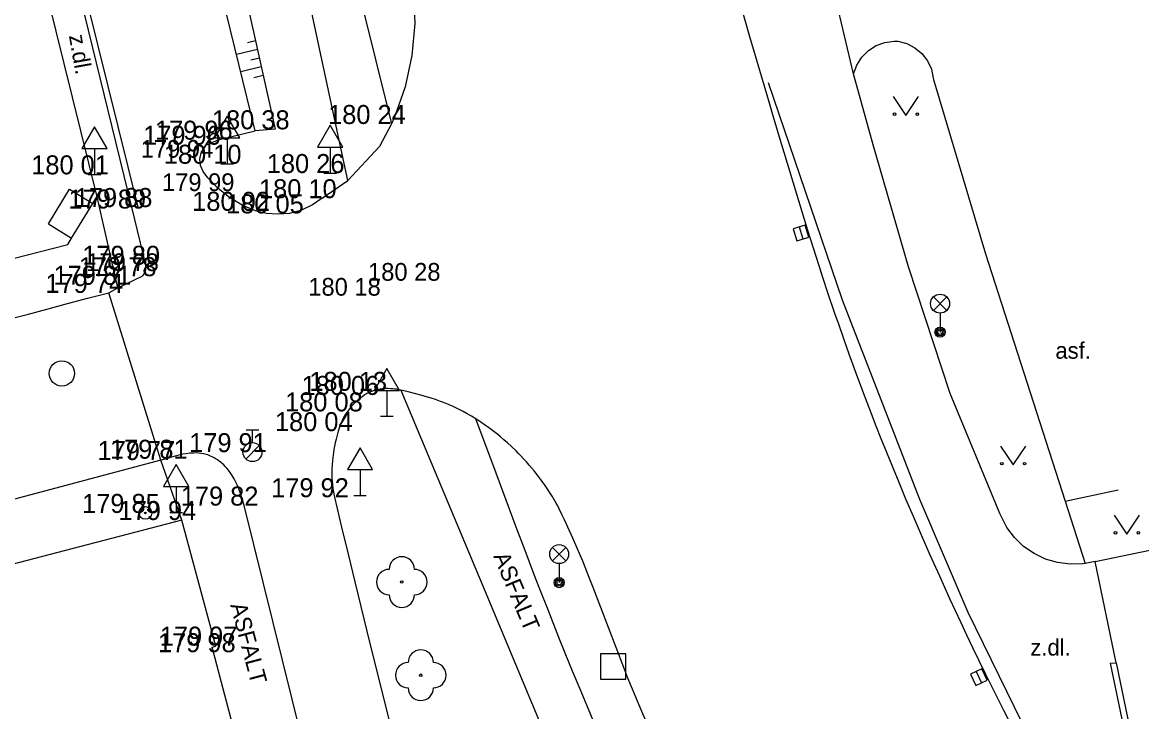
# Model space of a CAD drawing. Extents: x -538441 to -536770, y -1181008 to -1179809.
# Drawn here: x -537786.52 to -537742.3, y -1180705.34 to -1180678.12 of the extents above; entities that cross this region are included whole.
import ezdxf

# ---------------------------------------------------------------- set-up
doc = ezdxf.new("R2010")
doc.units = 0
for name, color, linetype in [('Vrstva 10', 7, 'Continuous'), ('Vrstva 11', 7, 'Continuous'), ('Vrstva 14', 7, 'Continuous'), ('Vrstva 15', 7, 'Continuous'), ('Vrstva 22', 7, 'Continuous'), ('Vrstva 25', 7, 'Continuous'), ('Vrstva 26', 7, 'Continuous'), ('Vrstva 27', 7, 'Continuous'), ('Vrstva 28', 7, 'Continuous'), ('Vrstva 33', 7, 'Continuous'), ('Vrstva 34', 7, 'Continuous'), ('Vrstva 36', 7, 'Continuous'), ('Vrstva 4', 7, 'Continuous'), ('Vrstva 40', 7, 'Continuous'), ('Vrstva 5', 7, 'Continuous'), ('Vrstva 7', 7, 'Continuous'), ('Vrstva 9', 7, 'Continuous')]:
    doc.layers.add(name, color=color, linetype=linetype)

msp = doc.modelspace()

# ---------------------------------------------------------------- linework, layer by layer
at = {"layer": 'Vrstva 10'}
for p, q in [((-537777.32, -1180682.4), (-537779.78, -1180672.39)), ((-537785.13, -1180673.46), (-537782.2, -1180685.47)), ((-537755.48, -1180686.34), (-537756.199, -1180683.987)), ((-537774.67, -1180685.06), (-537773.66, -1180684.36)), ((-537782.2, -1180685.47), (-537781.65, -1180687.69)), ((-537782.744, -1180688.603), (-537781.79, -1180688.14)), ((-537783.109, -1180688.798), (-537782.744, -1180688.603)), ((-537781.05, -1180695.4), (-537787.035, -1180697)), ((-537773.495, -1180714.32), (-537777.76, -1180697.2)), ((-537773.388, -1180700.211), (-537772.906, -1180702.164)), ((-537772.906, -1180702.164), (-537771.2, -1180709))]:
    msp.add_line(p, q, dxfattribs=at)
for points in [[(-537756.199, -1180683.987), (-537756.511, -1180682.957), (-537756.801, -1180681.991), (-537757.071, -1180681.086), (-537757.322, -1180680.236), (-537757.554, -1180679.439), (-537757.771, -1180678.692), (-537757.972, -1180677.991), (-537758.343, -1180676.675), (-537758.662, -1180675.522), (-537758.935, -1180674.513)], [(-537771.07, -1180676.89), (-537771.02, -1180678.163), (-537771.13, -1180679.42), (-537771.4, -1180680.668), (-537771.823, -1180681.866), (-537771.94, -1180682.13)], [(-537779.25, -1180682.95), (-537778.78, -1180682.75), (-537777.32, -1180682.4)], [(-537771.94, -1180682.13), (-537772.41, -1180683.017), (-537773.66, -1180684.36)], [(-537779.38, -1180684), (-537779.481, -1180683.77), (-537779.511, -1180683.516), (-537779.461, -1180683.265), (-537779.336, -1180683.042), (-537779.25, -1180682.95)], [(-537777.31, -1180685.56), (-537777.841, -1180685.334), (-537778.338, -1180685.037), (-537778.789, -1180684.674), (-537779.186, -1180684.253), (-537779.38, -1180684)], [(-537774.67, -1180685.06), (-537775.06, -1180685.328), (-537775.488, -1180685.527), (-537775.97, -1180685.66), (-537776.411, -1180685.697), (-537776.881, -1180685.663), (-537777.31, -1180685.56)], [(-537752.366, -1180695.104), (-537752.582, -1180694.564), (-537752.782, -1180694.058), (-537752.967, -1180693.582), (-537753.308, -1180692.688), (-537753.6, -1180691.903), (-537753.851, -1180691.214), (-537754.068, -1180690.61), (-537754.254, -1180690.08), (-537754.414, -1180689.616), (-537754.69, -1180688.801), (-537754.893, -1180688.188), (-537755.043, -1180687.727), (-537755.264, -1180687.035), (-537755.48, -1180686.34)], [(-537781.65, -1180687.69), (-537781.652, -1180687.886), (-537781.727, -1180688.066), (-537781.79, -1180688.14)], [(-537785.503, -1180689.432), (-537784.882, -1180689.263), (-537783.951, -1180689.003), (-537783.109, -1180688.798)], [(-537794.72, -1180691.65), (-537791.7, -1180690.945), (-537788.68, -1180690.24), (-537787.968, -1180690.07), (-537787.347, -1180689.916), (-537786.805, -1180689.778), (-537786.331, -1180689.654), (-537785.503, -1180689.432)], [(-537772.591, -1180692.647), (-537772.692, -1180692.68), (-537772.768, -1180692.711), (-537772.824, -1180692.737), (-537772.908, -1180692.78), (-537772.99, -1180692.83), (-537773.093, -1180692.9), (-537773.184, -1180692.967), (-537773.265, -1180693.033), (-537773.338, -1180693.097), (-537773.402, -1180693.158), (-537773.46, -1180693.216), (-537773.512, -1180693.273), (-537773.558, -1180693.327), (-537773.64, -1180693.43), (-537773.706, -1180693.524), (-537773.76, -1180693.609), (-537773.804, -1180693.685), (-537773.841, -1180693.752), (-537773.899, -1180693.873), (-537773.939, -1180693.967), (-537773.967, -1180694.038), (-537774.006, -1180694.148), (-537774.04, -1180694.26), (-537774.085, -1180694.422), (-537774.123, -1180694.575), (-537774.156, -1180694.719), (-537774.185, -1180694.854), (-537774.208, -1180694.981), (-537774.228, -1180695.1), (-537774.245, -1180695.212), (-537774.27, -1180695.421), (-537774.285, -1180695.605), (-537774.293, -1180695.765), (-537774.295, -1180695.905), (-537774.294, -1180696.027), (-537774.291, -1180696.133), (-537774.285, -1180696.226), (-537774.271, -1180696.389), (-537774.257, -1180696.51), (-537774.243, -1180696.6), (-537774.219, -1180696.736), (-537774.19, -1180696.87), (-537773.909, -1180698.057), (-537773.641, -1180699.169), (-537773.388, -1180700.211)], [(-537772.087, -1180692.579), (-537772.201, -1180692.581), (-537772.301, -1180692.59), (-537772.389, -1180692.601), (-537772.466, -1180692.615), (-537772.533, -1180692.631), (-537772.591, -1180692.647)], [(-537764.6, -1180698.878), (-537764.769, -1180698.488), (-537764.9, -1180698.197), (-537765.101, -1180697.762), (-537765.205, -1180697.546), (-537765.31, -1180697.33), (-537765.369, -1180697.213), (-537765.427, -1180697.106), (-537765.483, -1180697.006), (-537765.592, -1180696.822), (-537765.692, -1180696.664), (-537765.783, -1180696.528), (-537765.864, -1180696.41), (-537766.012, -1180696.207), (-537766.127, -1180696.056), (-537766.305, -1180695.832), (-537766.49, -1180695.61), (-537766.606, -1180695.475), (-537766.716, -1180695.352), (-537766.82, -1180695.24), (-537766.919, -1180695.137), (-537767.013, -1180695.042), (-537767.192, -1180694.869), (-537767.352, -1180694.723), (-537767.495, -1180694.597), (-537767.623, -1180694.49), (-537767.737, -1180694.398), (-537767.942, -1180694.239), (-537768.1, -1180694.122), (-537768.221, -1180694.036), (-537768.408, -1180693.907), (-537768.6, -1180693.78), (-537768.778, -1180693.668), (-537768.947, -1180693.57), (-537769.106, -1180693.483), (-537769.256, -1180693.406), (-537769.397, -1180693.338), (-537769.53, -1180693.277), (-537769.655, -1180693.222), (-537769.773, -1180693.173), (-537769.995, -1180693.087), (-537770.191, -1180693.017), (-537770.362, -1180692.96), (-537770.512, -1180692.912), (-537770.776, -1180692.835), (-537770.974, -1180692.782), (-537771.272, -1180692.708), (-537771.57, -1180692.64), (-537771.656, -1180692.623), (-537771.737, -1180692.608), (-537771.815, -1180692.597), (-537771.888, -1180692.589), (-537771.956, -1180692.584), (-537772.087, -1180692.579)], [(-537777.76, -1180697.2), (-537777.797, -1180697.059), (-537777.835, -1180696.927), (-537777.874, -1180696.802), (-537777.914, -1180696.686), (-537777.954, -1180696.577), (-537777.995, -1180696.476), (-537778.035, -1180696.382), (-537778.076, -1180696.296), (-537778.116, -1180696.216), (-537778.156, -1180696.142), (-537778.194, -1180696.074), (-537778.233, -1180696.011), (-537778.308, -1180695.897), (-537778.38, -1180695.802), (-537778.446, -1180695.721), (-537778.507, -1180695.654), (-537778.562, -1180695.597), (-537778.613, -1180695.549), (-537778.659, -1180695.509), (-537778.742, -1180695.442), (-537778.808, -1180695.394), (-537778.859, -1180695.361), (-537778.938, -1180695.313), (-537779.02, -1180695.27), (-537779.081, -1180695.242), (-537779.14, -1180695.218), (-537779.198, -1180695.197), (-537779.255, -1180695.18), (-537779.31, -1180695.166), (-537779.363, -1180695.154), (-537779.468, -1180695.137), (-537779.566, -1180695.127), (-537779.659, -1180695.123), (-537779.746, -1180695.124), (-537779.829, -1180695.127), (-537779.906, -1180695.134), (-537780.051, -1180695.152), (-537780.178, -1180695.174), (-537780.289, -1180695.197), (-537780.482, -1180695.244), (-537780.769, -1180695.322), (-537780.91, -1180695.362), (-537781.05, -1180695.4)], [(-537748.1, -1180704.58), (-537748.45, -1180703.87), (-537748.71, -1180703.336), (-537748.96, -1180702.817), (-537749.2, -1180702.314), (-537749.43, -1180701.827), (-537749.87, -1180700.881), (-537750.276, -1180699.992), (-537750.651, -1180699.156), (-537750.996, -1180698.371), (-537751.315, -1180697.633), (-537751.609, -1180696.941), (-537751.882, -1180696.29), (-537752.133, -1180695.678), (-537752.366, -1180695.104)], [(-537760.419, -1180708.658), (-537760.897, -1180707.725), (-537761.37, -1180706.79), (-537761.512, -1180706.503), (-537761.646, -1180706.223), (-537761.773, -1180705.951), (-537761.893, -1180705.687), (-537762.007, -1180705.429), (-537762.222, -1180704.928), (-537762.418, -1180704.456), (-537762.597, -1180704.011), (-537762.762, -1180703.593), (-537763.966, -1180700.437), (-537764.12, -1180700.043), (-537764.258, -1180699.7), (-537764.38, -1180699.4), (-537764.6, -1180698.878)], [(-537742.918, -1180713.862), (-537743.291, -1180713.255), (-537743.638, -1180712.685), (-537743.961, -1180712.148), (-537744.26, -1180711.643), (-537744.539, -1180711.169), (-537744.798, -1180710.723), (-537745.039, -1180710.303), (-537745.487, -1180709.514), (-537745.873, -1180708.82), (-537746.208, -1180708.21), (-537746.498, -1180707.674), (-537746.749, -1180707.204), (-537747.184, -1180706.378), (-537747.506, -1180705.755), (-537747.745, -1180705.286), (-537748.1, -1180704.58)]]:
    msp.add_lwpolyline(points, dxfattribs=at)
at = {"layer": 'Vrstva 11'}
for p, q in [((-537753.677, -1180680.146), (-537754.899, -1180675.016)), ((-537773.21, -1180676.96), (-537771.94, -1180682.13)), ((-537773.66, -1180684.36), (-537775.12, -1180677.55)), ((-537752.902, -1180682.952), (-537753.677, -1180680.146)), ((-537750.526, -1180680.376), (-537748.46, -1180687.263)), ((-537751.505, -1180687.767), (-537752.902, -1180682.952)), ((-537748.46, -1180687.263), (-537745.318, -1180697.03)), ((-537749.865, -1180692.778), (-537751.505, -1180687.767)), ((-537781.05, -1180695.4), (-537783.109, -1180688.798)), ((-537771.57, -1180692.64), (-537768.235, -1180700.595)), ((-537747.894, -1180697.509), (-537749.865, -1180692.778)), ((-537767.804, -1180695.915), (-537768.6, -1180693.78)), ((-537780.22, -1180697.77), (-537781.05, -1180695.4)), ((-537745.318, -1180697.03), (-537743.221, -1180696.584)), ((-537745.318, -1180697.03), (-537744.527, -1180699.488)), ((-537768.235, -1180700.595), (-537764.9, -1180708.55))]:
    msp.add_line(p, q, dxfattribs=at)
for points in [[(-537781.95, -1180685.41), (-537785.12, -1180672.6)], [(-537753.677, -1180680.146), (-537753.551, -1180679.801), (-537753.354, -1180679.492), (-537753.095, -1180679.232), (-537752.786, -1180679.034), (-537752.441, -1180678.908), (-537752.077, -1180678.86), (-537751.924, -1180678.863)], [(-537751.924, -1180678.863), (-537751.575, -1180678.954), (-537751.254, -1180679.119), (-537750.977, -1180679.35), (-537750.757, -1180679.637), (-537750.606, -1180679.965), (-537750.531, -1180680.318), (-537750.526, -1180680.376)], [(-537783.58, -1180685.01), (-537782.787, -1180688.484), (-537782.744, -1180688.603)], [(-537764.448, -1180704.539), (-537764.78, -1180703.733), (-537765.068, -1180703.026), (-537765.318, -1180702.407), (-537765.75, -1180701.322), (-537766.07, -1180700.506), (-537766.308, -1180699.893), (-537766.66, -1180698.973), (-537767.007, -1180698.05), (-537767.804, -1180695.915)], [(-537744.135, -1180699.406), (-537744.527, -1180699.488), (-537744.625, -1180699.502), (-537745.124, -1180699.518), (-537745.619, -1180699.454), (-537746.098, -1180699.313), (-537746.548, -1180699.096), (-537746.958, -1180698.811), (-537747.317, -1180698.464), (-537747.617, -1180698.065), (-537747.848, -1180697.622), (-537747.894, -1180697.509)], [(-537743.302, -1180703.409), (-537744.135, -1180699.406), (-537741.977, -1180698.957)], [(-537760.234, -1180713.791), (-537760.618, -1180713.042), (-537760.948, -1180712.385), (-537761.232, -1180711.807), (-537761.478, -1180711.3), (-537761.69, -1180710.855), (-537761.874, -1180710.465), (-537762.191, -1180709.78), (-537762.426, -1180709.264), (-537762.771, -1180708.489), (-537763.11, -1180707.71), (-537763.622, -1180706.511), (-537764.065, -1180705.46), (-537764.448, -1180704.539)]]:
    msp.add_lwpolyline(points, dxfattribs=at)
at = {"layer": 'Vrstva 14'}
for p, q in [((-537779.32, -1180669.8), (-537776.53, -1180682.34)), ((-537776.53, -1180682.34), (-537777.32, -1180682.4))]:
    msp.add_line(p, q, dxfattribs=at)
at = {"layer": 'Vrstva 15'}
for p, q in [((-537777.63, -1180678.915), (-537777.309, -1180678.839)), ((-537778.061, -1180679.376), (-537777.233, -1180679.18)), ((-537777.894, -1180680.057), (-537777.081, -1180679.865)), ((-537777.5, -1180679.603), (-537777.157, -1180679.522)), ((-537777.369, -1180680.291), (-537777.005, -1180680.205))]:
    msp.add_line(p, q, dxfattribs=at)
at = {"layer": 'Vrstva 22'}
for centre in [(-537771.53, -1180700.22), (-537770.78, -1180703.9)]:
    msp.add_circle(centre, 0.05, dxfattribs=at)
for centre, start, end in [((-537771.53, -1180699.72), 0, 180), ((-537772.03, -1180700.22), 90, 270), ((-537771.03, -1180700.22), 270, 90), ((-537771.53, -1180700.72), 180, 0), ((-537770.78, -1180703.4), 0, 180), ((-537771.28, -1180703.9), 90, 270), ((-537770.28, -1180703.9), 270, 90), ((-537770.78, -1180704.4), 180, 0)]:
    msp.add_arc(centre, 0.5, start, end, dxfattribs=at)
at = {"layer": 'Vrstva 25'}
for radius in [0.25, 0.0303]:
    msp.add_circle((-537781.66, -1180697.49), radius, dxfattribs=at)
at = {"layer": 'Vrstva 26'}
msp.add_lwpolyline([(-537763.682, -1180704.056), (-537762.682, -1180704.056), (-537762.682, -1180703.056), (-537763.682, -1180703.056)], close=True, dxfattribs=at)
at = {"layer": 'Vrstva 27'}
for p, q in [((-537755.831, -1180686.194), (-537755.685, -1180686.672)), ((-537748.839, -1180703.752), (-537748.619, -1180704.202))]:
    msp.add_line(p, q, dxfattribs=at)
for points in [[(-537756.07, -1180686.267), (-537755.924, -1180686.745), (-537755.446, -1180686.599), (-537755.592, -1180686.121)], [(-537749.063, -1180703.862), (-537748.844, -1180704.311), (-537748.395, -1180704.092), (-537748.614, -1180703.643)]]:
    msp.add_lwpolyline(points, close=True, dxfattribs=at)
msp.add_circle((-537784.96, -1180691.98), 0.5, dxfattribs=at)
at = {"layer": 'Vrstva 28'}
for p, q in [((-537777.68, -1180694.215), (-537777.18, -1180694.215)), ((-537777.43, -1180694.715), (-537777.43, -1180694.215)), ((-537777.688, -1180695.362), (-537777.158, -1180694.832))]:
    msp.add_line(p, q, dxfattribs=at)
msp.add_circle((-537777.43, -1180695.09), 0.375, dxfattribs=at)
at = {"layer": 'Vrstva 33'}
for p, q in [((-537750.527, -1180689.49), (-537749.997, -1180688.96)), ((-537750.527, -1180688.96), (-537749.997, -1180689.49)), ((-537750.262, -1180689.6), (-537750.262, -1180690.35)), ((-537765.576, -1180699.382), (-537765.046, -1180698.852)), ((-537765.576, -1180698.852), (-537765.046, -1180699.382)), ((-537765.311, -1180699.492), (-537765.311, -1180700.242))]:
    msp.add_line(p, q, dxfattribs=at)
for centre, radius in [((-537750.262, -1180689.225), 0.375), ((-537750.262, -1180690.35), 0.2), ((-537750.262, -1180690.35), 0.145), ((-537750.262, -1180690.35), 0.0876), ((-537765.311, -1180699.117), 0.375), ((-537765.311, -1180700.242), 0.2), ((-537765.311, -1180700.242), 0.145), ((-537765.311, -1180700.242), 0.0876)]:
    msp.add_circle(centre, radius, dxfattribs=at)
at = {"layer": 'Vrstva 34'}
for p, q in [((-537778.43, -1180682.682), (-537778.43, -1180683.7)), ((-537783.67, -1180683.102), (-537783.67, -1180684.12)), ((-537774.362, -1180683.049), (-537774.362, -1180684.067)), ((-537778.68, -1180683.7), (-537778.18, -1180683.7)), ((-537783.92, -1180684.12), (-537783.42, -1180684.12)), ((-537774.612, -1180684.067), (-537774.112, -1180684.067)), ((-537772.114, -1180692.653), (-537772.114, -1180693.671)), ((-537772.364, -1180693.671), (-537771.864, -1180693.671)), ((-537773.18, -1180695.78), (-537773.18, -1180696.798)), ((-537780.446, -1180696.449), (-537780.446, -1180697.467)), ((-537773.43, -1180696.798), (-537772.93, -1180696.798)), ((-537780.696, -1180697.467), (-537780.196, -1180697.467))]:
    msp.add_line(p, q, dxfattribs=at)
for points in [[(-537778.93, -1180682.682), (-537777.93, -1180682.682), (-537778.43, -1180681.816)], [(-537784.17, -1180683.102), (-537783.17, -1180683.102), (-537783.67, -1180682.236)], [(-537774.862, -1180683.049), (-537773.862, -1180683.049), (-537774.362, -1180682.183)], [(-537772.614, -1180692.653), (-537771.614, -1180692.653), (-537772.114, -1180691.787)], [(-537773.68, -1180695.78), (-537772.68, -1180695.78), (-537773.18, -1180694.914)], [(-537780.946, -1180696.449), (-537779.946, -1180696.449), (-537780.446, -1180695.583)]]:
    msp.add_lwpolyline(points, close=True, dxfattribs=at)
at = {"layer": 'Vrstva 36'}
for points in [[(-537752.108, -1180681.041), (-537751.608, -1180681.791), (-537751.108, -1180681.041)], [(-537747.871, -1180694.847), (-537747.371, -1180695.597), (-537746.871, -1180694.847)], [(-537743.378, -1180697.576), (-537742.878, -1180698.326), (-537742.378, -1180697.576)]]:
    msp.add_lwpolyline(points, dxfattribs=at)
for centre in [(-537752.058, -1180681.741), (-537751.159, -1180681.741), (-537747.821, -1180695.547), (-537746.922, -1180695.547), (-537743.328, -1180698.276), (-537742.429, -1180698.276)]:
    msp.add_circle(centre, 0.05, dxfattribs=at)
at = {"layer": 'Vrstva 5'}
for p, q in [((-537786.164, -1180674.56), (-537783.58, -1180685.01)), ((-537785.491, -1180686.073), (-537784.653, -1180684.704)), ((-537784.653, -1180684.704), (-537783.736, -1180685.265)), ((-537785.491, -1180686.073), (-537784.573, -1180686.634)), ((-537794.55, -1180689.39), (-537784.73, -1180686.89)), ((-537778.88, -1180702.75), (-537780.22, -1180697.77)), ((-537779.025, -1180702.789), (-537778.88, -1180702.75)), ((-537776.495, -1180712.379), (-537779.025, -1180702.789))]:
    msp.add_line(p, q, dxfattribs=at)
for points in [[(-537783.736, -1180685.265), (-537783.58, -1180685.01)], [(-537784.573, -1180686.634), (-537783.736, -1180685.265)], [(-537784.73, -1180686.89), (-537784.573, -1180686.634)], [(-537780.22, -1180697.77), (-537799.941, -1180702.915), (-537804.1, -1180704), (-537804.39, -1180704.075)]]:
    msp.add_lwpolyline(points, dxfattribs=at)
at = {"layer": 'Vrstva 7'}
for p, q in [((-537743.525, -1180703.429), (-537743.302, -1180703.409)), ((-537741.85, -1180711.5), (-537743.525, -1180703.429)), ((-537743.302, -1180703.409), (-537741.661, -1180711.313))]:
    msp.add_line(p, q, dxfattribs=at)
at = {"layer": 'Vrstva 9'}
for p, q in [((-537757.058, -1180680.492), (-537754.133, -1180689.07)), ((-537754.133, -1180689.07), (-537751.069, -1180696.941))]:
    msp.add_line(p, q, dxfattribs=at)
msp.add_lwpolyline([(-537751.069, -1180696.941), (-537749.158, -1180701.406), (-537747.028, -1180705.772)], dxfattribs=at)

# ---------------------------------------------------------------- texts
at = {"layer": 'Vrstva 4'}
for s, height, p in [('180 38 ', 0.75, (-537779.03, -1180682.34)), ('180 24 ', 0.75, (-537774.44, -1180682.13)), ('179 96 ', 0.75, (-537781.28, -1180682.75)), ('179 96 ', 0.75, (-537781.75, -1180682.95)), ('179 94 ', 0.7, (-537781.843, -1180683.46)), ('180 10 ', 0.75, (-537780.93, -1180683.7)), ('180 01 ', 0.75, (-537786.17, -1180684.12)), ('180 26 ', 0.75, (-537776.862, -1180684.067)), ('179 99 ', 0.7, (-537781.003, -1180684.78)), ('180 10 ', 0.75, (-537777.17, -1180685.06)), ('179 89 ', 0.75, (-537784.7, -1180685.47)), ('179 88 ', 0.75, (-537784.45, -1180685.41)), ('180 02 ', 0.75, (-537779.81, -1180685.56)), ('180 05 ', 0.75, (-537778.47, -1180685.66)), ('179 80 ', 0.75, (-537784.15, -1180687.69)), ('179 78 ', 0.75, (-537784.29, -1180688.14)), ('179 78 ', 0.7, (-537783.993, -1180687.94)), ('179 81 ', 0.75, (-537785.29, -1180688.48)), ('180 28 ', 0.7, (-537772.863, -1180688.32)), ('179 74 ', 0.75, (-537785.61, -1180688.8)), ('180 18 ', 0.7, (-537775.223, -1180688.91)), ('180 06 ', 0.75, (-537775.49, -1180692.83)), ('180 13 ', 0.75, (-537775.18, -1180692.67)), ('180 08 ', 0.75, (-537776.14, -1180693.48)), ('180 04 ', 0.75, (-537776.54, -1180694.26)), ('179 91 ', 0.75, (-537779.93, -1180695.09)), ('179 77 ', 0.75, (-537783.55, -1180695.4)), ('179 81 ', 0.75, (-537783.06, -1180695.35)), ('179 92 ', 0.75, (-537776.69, -1180696.87)), ('179 82 ', 0.75, (-537780.26, -1180697.2)), ('179 85 ', 0.75, (-537784.16, -1180697.49)), ('179 94 ', 0.75, (-537782.72, -1180697.77)), ('179 97 ', 0.75, (-537781.09, -1180702.73)), ('179 98 ', 0.75, (-537781.16, -1180702.99))]:
    msp.add_text(s, height=height, dxfattribs=at).set_placement(p)
at = {"layer": 'Vrstva 40'}
for s, rotation, p in [('z.dl.', 280, (-537784.684, -1180678.644)), ('ASFALT', 292.745, (-537767.922, -1180699.198)), ('ASFALT', 284.7788, (-537778.31, -1180701.125))]:
    msp.add_text(s, height=0.65, rotation=rotation, dxfattribs=at).set_placement(p)
for s, p in [('asf.', (-537745.704, -1180691.401)), ('z.dl.', (-537746.695, -1180703.122))]:
    msp.add_text(s, height=0.65, dxfattribs=at).set_placement(p)

doc.saveas('drawing.dxf')
